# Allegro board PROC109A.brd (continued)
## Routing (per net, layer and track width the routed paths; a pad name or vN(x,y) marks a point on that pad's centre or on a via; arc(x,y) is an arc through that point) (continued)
GPIO1_0: length 86
  TOP w0.102: v2(80.41,-47.86) 80.48,-47.81 U18.J3
  L03_SIG1 w0.121: v2(80.41,-47.86) 79.64,-48.63 79.64,-51.8 79.91,-52.07 79.91,-53.92 79.35,-54.48 79.35,-55.89 79.7,-56.24 v1(80.65,-56.24)
  BOTTOM w0.135: v1(80.65,-56.24) 80.36,-56.54 74.4,-56.54 73.39,-57.55 66.59,-57.55 66.53,-57.5 66.44,-57.5 64.4,-55.46 62.77,-55.46 62.16,-54.85 57.62,-54.85 57.61,-54.84 53.45,-54.84 52.45,-53.85 49.73,-53.85 46.54,-50.65 46.54,-40.66 49.28,-37.92 49.76,-37.92 53.89,-33.79 53.89,-23.96 58.53,-19.32 J2.15
GPIO1_1: length 83
  TOP w0.102: v2(80.41,-47.29) 80.46,-47.31 U18.J4
  L03_SIG1 w0.121: v2(80.41,-47.29) 80.78,-47.66 80.78,-51.54 80.31,-52 80.31,-55.32 v1(79.89,-55.74)
  BOTTOM w0.135: v1(79.89,-55.74) 79.44,-55.74 79.18,-56 73.97,-56 73.01,-56.96 66.75,-56.96 64.72,-54.92 63,-54.92 62.38,-54.3 53.69,-54.3 52.56,-53.17 50.05,-53.17 47.67,-50.79 47.67,-43.77 48.67,-42.77 48.67,-41.5 53.02,-37.15 53.02,-36.36 57.08,-32.3 57.08,-23.87 61.07,-19.88 J2.17
GPIO1_2: length 77.3
  TOP w0.102: U18.G1 79.89,-49.11 79.71,-49.3 79.71,-49.62
  TOP w0.135: 79.71,-49.62 79.71,-50.14 78.56,-51.28 78.56,-54.41 v1(77.67,-55.3)
  BOTTOM w0.135: J2.19 63.61,-19.32 59.88,-23.05 59.88,-32.7 49.4,-43.18 49.4,-45.57 48.51,-46.46 48.51,-50.49 50.38,-52.36 70.6,-52.36 72.69,-54.46 73.77,-54.46 74.61,-55.3 v1(77.67,-55.3)
GPIO1_3: length 93.5
  TOP w0.102: U18.H1 80.39,-49.12 80.53,-49.26 80.53,-49.58
  TOP w0.135: v1(80.37,-58.12) 78.83,-56.58 78.83,-51.68 79.63,-50.88 80.19,-50.88 80.53,-50.53 80.53,-49.58
  BOTTOM w0.135: J2.4 42.04,-16.74 42.04,-19.84 48.06,-25.86 48.06,-29.2 47.17,-30.08 47.17,-34.13 45.86,-35.45 45.86,-38.85 43.84,-40.87 43.84,-50.43 43.84,-51.51 49.7,-57.37 49.7,-57.37 49.71,-57.37 49.72,-57.38 49.98,-57.38 49.99,-57.38 50.02,-57.38 58.65,-57.38 58.81,-57.22 63.87,-57.22 65.77,-59.11 65.82,-59.11 66.38,-59.67 66.38,-60 67.1,-60.73 75.8,-60.73 78.02,-58.51 79.52,-58.51 79.92,-58.12 v1(80.37,-58.12)
GPIO1_4: length 91
  TOP w0.102: U18.K2 81.39,-48.42 81.11,-48.7 81.11,-48.93 81.34,-49.15 81.34,-49.66
  TOP w0.135: v1(82.42,-56.63) 82.42,-55.45 81.34,-54.36 81.34,-49.66
  BOTTOM w0.135: J2.8 47.09,-16.77 47.09,-22.73 48.59,-24.24 48.59,-29.93 48.56,-29.97 48.56,-33.09 48.59,-33.13 48.59,-33.54 47.64,-34.5 47.64,-37.96 44.6,-41 44.6,-50.24 51.2,-56.84 53.32,-56.84 58.17,-56.84 58.34,-56.67 64.09,-56.67 65.99,-58.57 66.04,-58.57 66.92,-59.45 66.92,-59.78 67.32,-60.19 73.84,-60.19 76,-58.03 76.42,-58.03 76.95,-58.56 77.37,-58.56 78.57,-57.36 82.14,-57.36 82.42,-57.08 v1(82.42,-56.63)
GPIO1_5: length 85.8
  TOP w0.102: U18.F2 79.38,-48.33 79.38,-49.01 79.17,-49.22 79.17,-49.66
  TOP w0.135: 79.17,-49.66 79.17,-49.92 78.52,-50.57 78.44,-50.57 77.27,-51.74 77.01,-51.74 76.73,-52.02 76.73,-56.31 v1(77.39,-56.97)
  BOTTOM w0.135: J2.16 57.25,-16.77 57.25,-19.58 52.58,-24.26 52.58,-33.81 48.77,-37.62 48.77,-37.97 46.18,-40.56 46.18,-50.67 51.54,-56.03 52.52,-56.03 57.63,-56.03 58.55,-55.12 62.05,-55.12 62.66,-55.73 64.29,-55.73 66.32,-57.76 66.42,-57.76 66.47,-57.82 73.55,-57.82 74.4,-56.97 v1(77.39,-56.97)
GPIO1_6: length 56
  TOP w0.102: U18.H2 80.71,-48.63 80.71,-49.1 80.8,-49.19 80.8,-49.66
  TOP w0.135: J5.15 119.18,-64.06 101.02,-64.06 98.68,-61.72 86.49,-61.72 83.02,-58.25 81.75,-58.25 79.63,-56.14 79.63,-56.09 79.46,-55.92 79.46,-55.56 79.63,-55.39 79.63,-52.98 79.91,-52.71 79.91,-51.99 79.68,-51.77 79.68,-51.41 79.93,-51.16 80.53,-51.16 80.8,-50.89 80.8,-49.66
GPIO1_8: length 108
  TOP w0.102: U18.H5 80.35,-46.81 79.87,-47.29 v2(79.85,-47.29)
  L03_SIG1 w0.121: v1(130.73,-56.59) 130.4,-56.26 125.66,-56.26 125.12,-56.79 107.07,-56.79 106.51,-56.24 98.22,-56.24 97.06,-57.4 89.31,-57.4 89.15,-57.57 81.82,-57.57 81.18,-56.93 79.66,-56.93 78.61,-55.88 78.61,-51.77 78.77,-51.61 78.77,-48.38 v2(79.85,-47.29)
  BOTTOM w0.135: v1(130.73,-56.59) 131.19,-56.14 131.19,-41.99 131.65,-41.52 131.65,-37.12 131.65,-30.61 131.19,-30.14 131.19,-18.16 128.52,-15.49 J6.20
GPIO1_12: length 52.6
  TOP w0.102: 81.61,-49.53 81.61,-49.03 U18.K1
  TOP w0.135: 81.61,-49.53 81.61,-54.05 84.57,-57.01 84.57,-58.81 v1(86.54,-60.78)
  BOTTOM w0.135: J1.9 52.69,-62.99 66.09,-62.99 67.55,-61.53 76.31,-61.53 78.51,-59.33 85.08,-59.33 v1(86.54,-60.78)
GPIO1_18: length 50.1
  TOP w0.102: U18.K4 v2(81.39,-47.86)
  L03_SIG1 w0.121: v2(81.39,-47.86) 81.65,-48.12 81.65,-54.89 v1(83.39,-56.63)
  BOTTOM w0.135: U50.1 91.42,-56.1 90.95,-55.63 88.02,-55.63 87.36,-54.97 86.81,-54.97 85.15,-56.63 v1(83.39,-56.63) 81.23,-58.78 79.27,-58.78 ; 79.27,-58.78 78.3,-58.78 76.08,-60.99 67.1,-60.99 65.64,-62.45 59.77,-62.45 J1.15 ; 79.27,-58.78 79.27,-58.79
GPIO1_19: length 51.2
  TOP w0.102: 79.44,-49.61 79.44,-49.24 79.58,-49.1 79.58,-48.63 U18.G2
  TOP w0.135: v1(77.19,-58.13) 77.82,-57.49 77.82,-56.34 77.14,-55.65 77.14,-53.31 77.65,-52.81 77.65,-51.81 79.44,-50.03 79.44,-49.61
  L03_SIG1 w0.121: J5.9 112.91,-62.71 99.45,-62.71 97.22,-60.49 91.1,-60.49 89.46,-58.85 77.91,-58.85 v1(77.19,-58.13)
GPIO1_20: length 88
  TOP w0.102: U18.L5 81.44,-46.81 v2(81.39,-46.77)
  L03_SIG1 w0.121: v2(81.39,-46.77) 81.03,-47.14 81.03,-49.55 81.4,-49.92 81.4,-55.54 v1(81.41,-55.55)
  BOTTOM w0.135: v1(81.41,-55.55) 81.09,-55.23 79.39,-55.23 78.89,-55.73 73.83,-55.73 72.88,-56.69 66.86,-56.69 64.83,-54.65 63.11,-54.65 62.49,-54.03 53.81,-54.03 52.67,-52.9 50.16,-52.9 47.94,-50.68 47.94,-46.27 48.82,-45.39 48.82,-43.01 54.23,-37.6 54.23,-36.02 57.73,-32.51 57.73,-30 58.53,-29.2 58.53,-23.13 62.33,-19.33 62.33,-16.77 J2.20
GPIO1_21: length 53.3
  TOP w0.102: U18.J2 80.91,-48.33 80.91,-49.01 81.07,-49.17 81.07,-49.62
  TOP w0.135: 81.07,-49.62 81.07,-51.24 80.32,-51.99 80.32,-55.17 86.6,-61.45 98.79,-61.45 101.13,-63.79 116.39,-63.79 118.24,-61.95 118.24,-59.92 J5.14
GPIO1_22: length 48.6
  TOP w0.102: U18.M2 82.39,-49.25 82.63,-49.48
  TOP w0.135: 82.63,-49.48 82.63,-50.37 83.13,-50.87 83.13,-53.92 85.38,-56.17 85.38,-57.11 86.23,-57.96 96.92,-57.96 98.06,-56.83 102.96,-56.83 103.33,-56.46 105.33,-56.46 106.28,-57.41 120.76,-57.41 J5.16
GPIO1_26: length 59.8
  TOP w0.102: U18.F5 v2(79.39,-46.36)
  TOP w0.135: J5.18 122.62,-56.73 117.36,-56.73 116.99,-57.1 115.47,-57.1 115.1,-56.73 v1(106.4,-56.73)
  L03_SIG1 w0.121: v1(106.4,-56.73) 106.24,-56.57 98.37,-56.57 97.28,-57.66 89.42,-57.66 89.25,-57.82 81.62,-57.82 80.98,-57.18 79.51,-57.18 78.26,-55.93 78.26,-54.69 77.65,-54.08 77.65,-51.54 78.46,-50.72 78.46,-48.35 79.39,-47.42 v2(79.39,-46.36)
GPIO1_31: length 52.3
  TOP w0.102: U18.P1 83.39,-49.41 83.58,-49.59
  TOP w0.135: J5.20 124.6,-56.16 117.55,-56.16 116.99,-56.72 116.09,-56.72 116.05,-56.76 115.7,-56.76 115.66,-56.72 115.47,-56.72 114.92,-56.16 103.25,-56.16 102.85,-56.56 97.95,-56.56 96.81,-57.69 87.57,-57.69 86.7,-56.83 86.7,-54.92 83.96,-52.19 83.96,-50.56 83.58,-50.17 83.58,-49.59
GPIO1_32: length 96.2
  TOP w0.102: U18.P2 83.71,-48.63 83.71,-49.34 83.85,-49.48
  TOP w0.135: v1(129.59,-55.45) 129.14,-55.9 117.43,-55.9 116.88,-56.45 116.44,-56.45 116.31,-56.31 116.31,-55.96 116.24,-55.9 103.13,-55.9 102.74,-56.29 97.84,-56.29 96.7,-57.43 87.9,-57.43 87.73,-57.25 87.73,-55.28 85.09,-52.64 85.09,-51.31 83.85,-50.06 83.85,-49.48
  BOTTOM w0.135: J6.17 126.78,-20.24 128.68,-20.24 130.36,-21.93 130.36,-30.46 130.85,-30.94 130.85,-37.45 130.85,-41.19 130.38,-41.66 130.38,-50.75 129.13,-51.99 129.13,-54.99 v1(129.59,-55.45)
GPIO1_33: length 85.2
  TOP w0.102: v2(84.93,-47.33) 84.92,-47.31 U18.T4
  L03_SIG1 w0.121: v2(84.93,-47.33) 85.33,-46.93 88,-46.93 89.06,-47.99 101.45,-47.99 101.83,-48.36 102.74,-48.36 104.34,-49.96 106.55,-49.96 107.72,-51.13 110.69,-51.13 111.75,-52.19 115.67,-52.19 116.15,-51.71 117.34,-51.71 118.53,-52.9 124.47,-52.9 124.81,-52.56 v1(129.57,-52.56)
  BOTTOM w0.135: J6.19 130.63,-21.56 130.63,-30.35 131.12,-30.83 131.12,-37.34 131.12,-41.3 130.65,-41.77 130.65,-51.48 v1(129.57,-52.56)
GPIO1_35: length 88.4
  TOP w0.102: U18.M4 81.93,-47.31 v2(81.91,-47.29)
  L03_SIG1 w0.121: v2(81.91,-47.29) 81.91,-54.48 84.41,-56.97 85.19,-56.97 85.83,-56.34 89,-56.34 89.56,-56.89 96.68,-56.89 97.89,-55.68 112.92,-55.68 113.15,-55.45 v1(113.59,-55.45)
  BOTTOM w0.135: J6.4 105.51,-16.77 105.51,-20.52 105.23,-20.8 105.23,-21.49 105.68,-21.94 110.02,-21.94 110.26,-22.17 110.26,-24.34 111.46,-25.54 111.46,-32.12 111.48,-32.15 111.48,-34.34 113.99,-36.85 113.99,-36.85 114,-36.87 114,-36.88 114.01,-36.89 114.01,-50.81 114,-50.82 114,-50.84 113.99,-50.85 113.99,-50.86 113.59,-51.26 v1(113.59,-55.45)
GPIO1_36: length 37.5
  TOP w0.102: v2(83.94,-47.86) 83.98,-47.81 U18.T3
  L03_SIG1 w0.102: v2(83.94,-47.86) 83.94,-48.22 85.37,-49.66
  L03_SIG1 w0.121: v1(116.18,-52.93) 115.95,-52.7 110.84,-52.7 109.99,-51.85 98.79,-51.85 97.46,-50.52 86.23,-50.52 85.37,-49.66
  BOTTOM w0.135: v1(116.18,-52.93) 116.51,-52.6 116.51,-52.1 116.74,-51.87 U52.3
GPIO1_36/PERIF_OUT_EN: length 59.3
  TOP w0.135: J6.8 113.08,-16.7 113.08,-18.54 114.33,-19.79 115.57,-19.79 116.15,-20.37 116.71,-20.37 116.76,-20.32 119.94,-20.32 123.11,-23.5 123.11,-27.58 120.02,-30.68 120.02,-32.56 120.56,-33.11 120.93,-33.11 122.76,-34.94 124.08,-34.94 125.67,-36.52 125.67,-36.88 124.81,-37.74 124.81,-38.15 125.07,-38.41 125.07,-40.41 124.54,-40.94 124.54,-45.11 123.88,-45.77 123.88,-48.79 122.9,-49.77 121.27,-49.77 119.09,-51.96 116.75,-51.96 116.36,-51.56 116.36,-50.46 v1(116.92,-49.89) 116.92,-49.88
  BOTTOM w0.135: U52.5 118.09,-50.55 117.94,-50.39 117.33,-50.39 117.2,-50.26 117.2,-50.11 116.97,-49.89 116.97,-49.89 v1(116.92,-49.89)
GPIO1_40: length 117.7
  TOP w0.102: U18.E4 78.36,-46.78 v2(78.36,-46.77)
  L03_SIG1 w0.121: v1(54.61,-39.24) 54.61,-40.23 56.07,-41.69 63.64,-41.69 66.22,-44.27 66.22,-45.15 69.52,-48.46 71.7,-48.46 73.47,-50.23 74.3,-50.23 77.76,-46.77 v2(78.36,-46.77)
  BOTTOM w0.135: J6.16 119.24,-12.71 86.4,-12.71 84.42,-14.68 84.42,-15.52 82.82,-17.12 66.44,-17.12 62.84,-20.73 62.84,-26.45 60.49,-28.8 60.49,-33.36 v1(54.61,-39.24)
GPIO1_41: length 124.3
  TOP w0.102: U18.D2 78.11,-48.6 78.11,-49.33 77.78,-49.66
  TOP w0.135: 77.78,-49.66 77.23,-50.21 77.22,-50.21 76.78,-50.65 76.48,-50.65 75.37,-51.75 75.37,-59.02 75.68,-59.32 78.01,-59.32 78.52,-58.82 82.83,-58.82 86.3,-62.3 98.5,-62.3 100.8,-64.6 100.82,-64.6 101.02,-64.8 120.17,-64.8 120.28,-64.91 127.44,-64.91 128.15,-64.2 129.33,-64.2 129.44,-64.31 129.55,-64.31 129.83,-64.59 v1(130.28,-64.59)
  BOTTOM w0.135: v1(130.28,-64.59) 130.28,-55.91 130.92,-55.27 130.92,-41.88 131.39,-41.41 131.39,-37.23 131.39,-30.72 130.9,-30.24 130.9,-19.08 128.58,-16.76 125.84,-16.76 J6.18
GPIO1_61: length 2.6
  TOP w0.135: TP34.1 158.72,-51.4 U22.7
GPIO1_77: length 98.5
  TOP w0.102: U18.B17 77.11,-41.09 76.48,-41.09 76.33,-40.94 76.05,-40.94
  TOP w0.135: v1(68.35,-38.58) 68.38,-38.55 70.33,-38.55 71.98,-40.21 72.8,-40.21 73.53,-40.94 76.05,-40.94
  BOTTOM w0.135: J6.13 118.21,-16.76 118.21,-14.83 116.35,-12.98 86.51,-12.98 84.69,-14.79 84.69,-15.63 82.93,-17.39 82.71,-17.39 66.55,-17.39 63.11,-20.84 63.11,-24.2 68.16,-29.25 71.41,-29.25 72.14,-29.97 72.14,-31.5 69.62,-34.02 69.62,-34.52 68.35,-35.79 v1(68.35,-38.58)
GPIO1_78: length 107.7
  TOP w0.102: U18.C16 77.89,-41.74 v2(77.86,-41.77)
  TOP w0.135: J6.15 120.78,-16.79 120.78,-14.53 119.39,-13.14 85.34,-13.14 81.81,-16.66 76.91,-16.66 75.11,-14.86 69.62,-14.86 67.61,-16.87 67.61,-29.62 66.66,-30.57 63.33,-30.57 62.51,-31.39 62.51,-36.34 61.89,-36.95 v1(61.89,-38.56)
  L03_SIG1 w0.121: v2(77.86,-41.77) 77.6,-42.03 77.15,-42.03 76.35,-42.82 71.15,-42.82 69.75,-44.22 67.94,-44.22 67.44,-43.71 67.44,-41.87 66.52,-40.94 64.75,-40.94 62.37,-38.56 v1(61.89,-38.56)
GPIO_OSPI0_RESET_N: length 36
  TOP w0.102: U18.M20 82.69,-39.02 82.69,-38.42 83.06,-38.04 83.06,-37.97
  TOP w0.135: 83.06,-37.97 83.06,-31.9 85.29,-29.67 85.29,-23.3 83.53,-21.54 v1(83.08,-21.54)
  BOTTOM w0.135: 75.2,-21.06 75.2,-21.45 75.74,-21.99 U31.1 ; 75.2,-21.06 75.75,-21.06 75.9,-20.92 75.9,-18.85 76.25,-18.49 83.16,-18.49 83.79,-19.13 83.79,-20.83 v1(83.08,-21.54) ; 75.2,-21.06 R181.1
GPIO_RGMII1_PHY_RSTN: length 100.7
  TOP w0.102: U18.Y19 86.67,-40.09 87.16,-40.09 87.74,-39.52 87.74,-39.49
  TOP w0.135: v1(95.6,-36.08) 95.15,-36.08 95.13,-36.09 94.08,-36.09 93.15,-37.02 90.21,-37.02 87.74,-39.49
  L03_SIG1 w0.121: v1(113.45,-33.31) 110.73,-36.03 102.2,-36.03 101.85,-35.69 99.19,-35.69 98.8,-36.08 v1(95.6,-36.08)
  BOTTOM w0.135: U43.1 142.44,-56.37 142.58,-56.22 142.58,-55.81 ; v1(113.45,-33.31) 113.45,-34.45 115.39,-36.4 115.39,-53.98 117.87,-56.45 118.26,-56.86 118.26,-62.66 120.62,-65.02 126.19,-65.02 126.88,-65.72 126.89,-65.72 126.9,-65.73 126.91,-65.73 126.93,-65.74 128.83,-65.74 128.84,-65.73 128.85,-65.73 128.87,-65.72 129,-65.58 129.23,-65.63 129.25,-65.63 129.49,-65.63 132.72,-65.63 132.74,-65.63 132.75,-65.62 133.44,-64.94 133.45,-64.92 133.45,-64.9 133.45,-55.68 135.48,-53.65 136.86,-53.65 136.88,-53.64 136.98,-53.65 137.62,-53.65 138.66,-54.69 140.79,-54.69 141.92,-55.81 142.58,-55.81 ; 142.58,-55.81 R275.1
GPIO_RGMII2_PHY_RSTN: length 63
  TOP w0.102: U18.Y15 87.56,-41.82 87.62,-41.88 87.74,-41.88
  TOP w0.135: 87.74,-41.88 94.47,-41.88 97.52,-38.83 101.88,-38.83 102.49,-38.23 104.85,-38.23 106.79,-36.29 108.46,-36.29 108.68,-36.07 121.69,-36.07 122.76,-37.13 123.7,-37.13 v1(124.16,-37.59)
  L03_SIG1 w0.121: v1(140.97,-35.56) 140.66,-35.87 139.35,-35.87 138.87,-35.39 138.19,-35.39 137.92,-35.66 125.15,-35.66 124.47,-36.34 124.47,-37.28 v1(124.16,-37.59)
  BOTTOM w0.135: 142.03,-36.76 R236.1 ; 142.03,-36.76 141.73,-37.06 141.17,-37.06 140.92,-36.81 U34.1 ; 142.03,-36.76 141.29,-36.02 141.29,-35.88 v1(140.97,-35.56)
LED1: length 45.5
  TOP w0.135: LD15.1 v1(176.75,-64.55)
  L03_SIG1 w0.121: v1(159.44,-34.67) 158.37,-35.74 158.37,-51.39 159.73,-52.75 159.73,-54.15 165.12,-59.54 166.42,-59.54 167.67,-60.78 167.67,-61.54 171.7,-65.58 175.72,-65.58 v1(176.75,-64.55)
  BOTTOM w0.135: v1(159.44,-34.67) U35.3
LED2: length 42.2
  TOP w0.135: LD14.1 v1(175.23,-64.55)
  L03_SIG1 w0.121: v1(159.44,-35.94) 158.62,-36.75 158.62,-51.28 160.02,-52.68 160.02,-54.08 165.23,-59.28 167.21,-59.28 170.33,-62.41 170.33,-63.65 171.96,-65.28 174.5,-65.28 v1(175.23,-64.55)
  BOTTOM w0.135: U35.4 v1(159.44,-35.94)
LED3: length 38.9
  TOP w0.135: LD13.1 v1(173.73,-64.55)
  L03_SIG1 w0.121: v1(173.73,-64.55) 173.26,-65.02 172.08,-65.02 170.81,-63.75 170.81,-62.48 167.36,-59.03 165.33,-59.03 160.32,-54.02 160.32,-49.89 158.88,-48.44 158.88,-37.77 v1(159.44,-37.21)
  BOTTOM w0.135: U35.5 v1(159.44,-37.21)
LED4: length 35.1
  TOP w0.135: LD12.1 v1(172.23,-64.55)
  L03_SIG1 w0.121: v1(159.44,-38.48) 159.16,-38.76 159.16,-47.85 160.59,-49.28 160.59,-53.92 165.43,-58.77 167.48,-58.77 172.23,-63.52 v1(172.23,-64.55)
  BOTTOM w0.135: U35.6 v1(159.44,-38.48)
LED_DRV_A0: length 2.6
  BOTTOM w0.135: U35.9 151.03,-41.02 150.93,-41.12 R245.2
LED_DRV_A1: length 2.6
  BOTTOM w0.135: R241.2 150.77,-39.6 150.93,-39.75 U35.10
LED_DRV_A2: length 2.9
  BOTTOM w0.135: U35.7 159.44,-39.75 159.66,-39.97 R243.2
LMK_1G: length 1.9
  TOP w0.135: U6.2 R32.1
LMK_CLK_IN: length 2.6
  TOP w0.135: U6.1 117.21,-25.19 116.93,-24.91 R26.2
LMK_CLK_IN_R: length 1.6
  TOP w0.135: R26.1 114.61,-24.32 U3.3
MAIN_UART0_RXD: length 63.3
  TOP w0.102: 76.05,-44.74 76.16,-44.74 76.23,-44.67 76.25,-44.67 76.61,-44.31 U18.B10
  TOP w0.135: 76.05,-44.74 73.38,-44.74 73.21,-44.91 71.83,-44.91 71.62,-44.7 69.75,-44.7 68.66,-45.8 67.26,-45.8 65.58,-44.11 63.53,-44.11 62.65,-44.99 v1(62.65,-45.63)
  L03_SIG1 w0.127: v1(62.65,-45.63) 63.22,-46.19 63.22,-53.55 60.6,-56.16 40.89,-56.16 34.39,-62.66 32.51,-62.66 32.05,-62.2 v1(32.05,-61.59)
  BOTTOM w0.135: U45.6 32.98,-61.2 32.59,-61.59 v1(32.05,-61.59)
MAIN_UART0_TXD: length 61.5
  TOP w0.102: 76.05,-44.47 76.16,-44.47 76.32,-44.31 76.32,-44.25 76.46,-44.11 77.1,-44.11 U18.B11
  TOP w0.135: 76.05,-44.47 73.26,-44.47 73.14,-44.6 71.9,-44.6 71.73,-44.43 69.62,-44.43 69.16,-44.88 66.8,-44.88 65.56,-43.64 63.45,-43.64 62.2,-44.88 62.2,-46.22 v1(62.57,-46.58)
  L03_SIG1 w0.121: v1(33.15,-61.65) 34.06,-60.73 35,-60.73 40.97,-54.76 60.55,-54.76
  L03_SIG1 w0.127: 60.55,-54.76 61.87,-53.44 61.87,-47.27 v1(62.57,-46.58)
  BOTTOM w0.135: v1(33.15,-61.65) 33.15,-62.12 R592.1 33.9,-61.97 33.9,-61.5 34.28,-61.11 U45.4
MAIN_UART1_CTS#: length 72.1
  TOP w0.102: v2(77.86,-43.36) 77.89,-43.39 U18.C11
  TOP w0.135: U12.11 98.65,-33.65 98.02,-34.29 98.02,-36.8 97.43,-37.39 93.96,-37.39 93.55,-37.8 v1(92.33,-37.8)
  L03_SIG1 w0.102: 77.06,-43.94 77.28,-43.94 v2(77.86,-43.36)
  L03_SIG1 w0.127: v1(68.1,-45.34) 68.61,-45.86 75.15,-45.86 77.06,-43.94
  BOTTOM w0.135: v1(92.33,-37.8) 92.33,-38.24 92.58,-38.5 92.58,-40.36 94.03,-41.81 94.03,-50.38 90.42,-53.99 88.67,-53.99 88.03,-53.35 86.07,-53.35 85.58,-53.84 75.02,-53.84 72.33,-51.15 68.82,-51.15 68.32,-50.65 68.32,-49.87 67.78,-49.32 67.78,-45.66 v1(68.1,-45.34)
MAIN_UART1_RTS#: length 107.9
  TOP w0.114: U18.A11 76.44,-43.81 76.32,-43.94
  TOP w0.135: v1(97.46,-64.02) 96.41,-64.02 95.76,-63.38 85.86,-63.38 82.38,-59.9 78.96,-59.9 78.12,-60.74 67.21,-60.74 66.57,-60.09 66.57,-56.47 66.78,-56.26 66.78,-52.68 66,-51.9 66,-51.21 65.46,-50.67 65,-50.67 63.22,-48.89 63.22,-47.98 61.94,-46.7 61.94,-44.77 63.34,-43.37 65.85,-43.37 67.09,-44.61 69.03,-44.61 69.48,-44.16 71.9,-44.16 72.07,-44.33 73.02,-44.33 73.15,-44.2 76.06,-44.2 76.32,-43.94 ; v1(108.9,-32.99) 108.89,-33.01 U12.5
  BOTTOM w0.135: v1(97.46,-64.02) 98.1,-64.02 98.68,-63.44 98.68,-58.11 97.97,-57.41 97.97,-51.11 97.76,-50.9 97.76,-40.31 105.08,-32.99 v1(108.9,-32.99)
MAIN_UART1_RXD: length 105
  TOP w0.102: 76.05,-43.44 76.46,-43.04 77.11,-43.04 U18.B12
  TOP w0.135: v1(102.95,-31.67) 102.91,-31.71 U12.8 ; 76.05,-43.44 75.83,-43.66 74.04,-43.66 73.39,-43.01 71.59,-43.01 71.04,-43.56 69.32,-43.56 69.09,-43.79 68.81,-44.07 67.65,-44.07 66.4,-42.83 62.99,-42.83 61.4,-44.42 61.4,-47.16 61.99,-47.75 61.99,-48.91 66.24,-53.16 66.24,-55.98 66.03,-56.19 66.03,-60.37 66.94,-61.27 78.35,-61.27 79.19,-60.44 82.16,-60.44 85.85,-64.13 v1(95.38,-64.13)
  BOTTOM w0.135: v1(102.95,-31.67) 102.63,-31.98 102.63,-32.41 98.35,-36.7 98.35,-37.71 96.68,-39.38 96.68,-51.34 96.89,-51.55 96.89,-58.88 97.02,-59 97.02,-62.02 95.38,-63.66 v1(95.38,-64.13)
MAIN_UART1_TXD: length 108.5
  TOP w0.102: U18.A12 76.6,-43.61 76.27,-43.61 76.05,-43.82
  TOP w0.135: 76.05,-43.82 75.95,-43.93 73.04,-43.93 72.91,-44.06 72.23,-44.06 72.06,-43.89 69.37,-43.89 68.92,-44.34 67.3,-44.34 66.06,-43.1 63.1,-43.1 61.67,-44.53 61.67,-46.93 62.26,-47.53 62.26,-48.8 66.51,-53.05 66.51,-56.14 66.3,-56.36 66.3,-60.25 67.05,-61.01 78.24,-61.01 79.07,-60.17 82.27,-60.17 85.81,-63.7 95.71,-63.7 96.46,-64.45 98.67,-64.45 v1(99.11,-64.01) ; v1(108.9,-34.95) 108.84,-34.95 108.83,-34.95 U12.2
  BOTTOM w0.135: v1(99.11,-64.01) 99.11,-58.17 98.24,-57.29 98.24,-50.99 98.03,-50.79 98.03,-40.68 103.76,-34.95 v1(108.9,-34.95)
MAIN_UART2_RXD: length 132.8
  L03_SIG1 w0.121: J1.5 48.77,-64.16 65.15,-64.16 66.22,-65.23 68.83,-65.23 68.84,-65.23 68.85,-65.23 68.86,-65.22 68.87,-65.21 73.68,-60.41 85.92,-60.41 86.11,-60.61 86.11,-60.96 86.36,-61.21 87.81,-61.21 92.65,-66.05 127.96,-66.05 v1(129.29,-64.72)
  BOTTOM w0.135: v1(129.29,-64.72) 129.29,-64.27 129.29,-64.26 129.29,-55.78 128.83,-55.32 128.83,-51.92 130.11,-50.64 130.11,-41.47 130.58,-41 130.58,-37.56 130.58,-31.05 129.69,-30.17 126.43,-30.17 125.95,-29.68 125.95,-28.39 125.66,-28.11 U32.16
MAIN_UART2_TXD: length 105.3
  TOP w0.102: 84.48,-37.97 84.48,-38.18 84.19,-38.47 84.19,-39.02 U18.R20
  TOP w0.135: 84.48,-37.97 84.48,-37.67 85.05,-37.1 85.05,-35.45 88.52,-31.98 v1(88.52,-30.81) 88.52,-29.83 R56.1
  L03_SIG1 w0.121: v1(38.3,-27.81) 43.15,-27.81 43.38,-28.04 55.28,-28.04 55.8,-28.57 64.72,-28.57 68.95,-24.33 72.21,-24.33 72.85,-24.98 82.39,-24.98 84.1,-26.69 84.1,-27.63 85.74,-29.27 87.95,-29.27 88.52,-29.84 v1(88.52,-30.81)
  BOTTOM w0.135: v1(38.3,-27.81) 38.86,-28.37 38.86,-32.58 40.49,-34.21 40.88,-34.21 41.43,-34.77 41.43,-49.56 47.09,-55.22 47.09,-59.94 J1.7
MAIN_UART4_RXD: length 22.4
  TOP w0.102: U18.L1 81.89,-49.66
  TOP w0.135: 81.89,-49.66 81.89,-53.45 84.84,-56.39 84.84,-57.33 88.56,-61.05 92.77,-61.05 92.87,-60.95 v1(93.32,-60.95)
  BOTTOM w0.135: v1(93.32,-60.95) 93.23,-61.04 92.84,-61.04 92.62,-60.82 U50.9 U50.4
MAIN_UART4_RXD/GPIO1_69: length 18.7
  TOP w0.135: v1(93.96,-60.01) 93.94,-60 93.94,-59.92 94.26,-60.24 94.63,-60.6 98.32,-60.6 101.24,-63.53 107.01,-63.53 J5.5
  BOTTOM w0.135: U50.7 93.84,-60.04 93.87,-60.01 v1(93.96,-60.01)
MAIN_UART4_TXD: length 48.5
  TOP w0.102: U18.E2 79.17,-48.59 79.17,-48.93 78.9,-49.21 78.9,-49.66
  TOP w0.135: 78.9,-49.66 78.9,-49.8 78.4,-50.3 78.33,-50.3 77.16,-51.47 76.91,-51.47 76.47,-51.91 76.47,-58.1 77.04,-58.67 77.86,-58.67 v1(78.45,-58.08)
  L03_SIG1 w0.127: J5.7 110.62,-59.97 97.38,-59.97 96.95,-59.54 94.81,-59.54 94.66,-59.68 94.28,-59.68 94.06,-59.46 90.43,-59.46 89.56,-58.59 89.52,-58.59 78.96,-58.59 v1(78.45,-58.08)
MCAN0_H: length 9.4
  BOTTOM w0.104: U44.7 164.52,-57.97 164.71,-58.15 164.71,-58.85 R278.1 164.35,-59.75 164.45,-59.85 164.57,-59.85 164.67,-59.96 164.67,-60.52 165.61,-61.46 165.61,-62.84 165.4,-63.04 164.16,-63.04 163.3,-63.9 J11.1
MCAN0_L: length 9.3
  BOTTOM w0.104: J11.3 167.19,-63.04 166.09,-63.04 165.89,-62.84 165.89,-61.34 164.95,-60.4 164.95,-59.96 165.05,-59.85 165.17,-59.85 165.27,-59.75 R277.2 164.98,-58.92 164.98,-58.15 165.17,-57.97 U44.6
MCAN0_RX: length 9.7
  BOTTOM w0.135: R263.2 160.87,-51.12 161.34,-50.65 165.94,-50.65 166.6,-51.31 166.6,-53.01 165.82,-53.79 U44.4
MCAN0_RX_MUX: length 114.9
  TOP w0.102: U18.A14 76.4,-42.32 76.3,-42.21 76.07,-42.21 76.05,-42.19
  TOP w0.135: 76.05,-42.19 71.22,-42.19 70.79,-42.63 68.56,-42.63 68.28,-42.34 v1(68.25,-42.34) ; U22.6 v1(156.37,-51.9)
  L03_SIG1 w0.121: v1(92.46,-52.68) 92.88,-52.26 97.72,-52.26 99.82,-54.35 105.63,-54.35 105.85,-54.13 113.63,-54.13 113.63,-54.13 115.36,-54.13 116.6,-55.37 124.74,-55.37 125.61,-54.51 131.59,-54.51 132.64,-55.55 138.68,-55.55 139.39,-56.25 149.82,-56.25 153.26,-52.81 155.47,-52.81 v1(156.37,-51.9)
  BOTTOM w0.135: v1(68.25,-42.34) 67.42,-43.17 67.42,-50.41 68.43,-51.42 72.09,-51.42 74.78,-54.11 85.69,-54.11 86.18,-53.62 87.91,-53.62 88.56,-54.26 90.88,-54.26 v1(92.46,-52.68)
MCAN0_RX_SYNC3_OUT: length 3.7
  TOP w0.135: v1(159.89,-51.89) 159.89,-51.89 R131.1 159.64,-50.9 U22.8
  BOTTOM w0.135: v1(159.89,-51.89) 159.89,-51.16 R131.1
MCAN0_STB: length 104.3
  TOP w0.102: v2(78.44,-47.86) 78.48,-47.81 U18.E3
  L03_SIG1 w0.121: v1(158.17,-61.54) 157.08,-62.63 142.37,-62.63 140.16,-60.42 140.16,-59.06 138.17,-57.08 106.65,-57.08 106.58,-57.15 106.23,-57.15 105.94,-56.86 98.51,-56.86 97.46,-57.91 89.53,-57.91 89.36,-58.08 81.5,-58.08 80.86,-57.44 79.21,-57.44 76.69,-54.92 76.69,-52.01 78.03,-50.67 78.03,-48.27 v2(78.44,-47.86)
  BOTTOM w0.135: v1(158.17,-61.54) 160.88,-61.54 162.11,-60.32 R276.2 163.77,-58.12 163.87,-58.01 U44.8
MCAN0_T: length 6.1
  L03_SIG1 w0.121: v1(163.37,-60.17) v1(166.25,-60.17)
  BOTTOM w0.135: R278.2 v1(163.37,-60.17) ; R277.1 v1(166.25,-60.17) 166.51,-60.43 167.1,-60.43 C267.1
MCAN0_TX: length 3.7
  BOTTOM w0.135: U44.1 163.87,-53.86 163.52,-53.52 R259.2
MCAN0_TX_EQEP2_I: length 150.5
  TOP w0.102: 76.05,-42.82 U18.B13
  TOP w0.135: 76.05,-42.82 76.01,-42.82 75.95,-42.75 75.94,-42.75 75.93,-42.74 71.46,-42.74 70.93,-43.27 69.19,-43.27 68.66,-43.8 67.76,-43.8 66.51,-42.56 62.88,-42.56 61.13,-44.31 61.13,-47.27 61.72,-47.86 61.72,-49.02 65.13,-52.42 65.13,-55.55 65.76,-56.18 65.76,-60.48 66.98,-61.7 69.22,-61.7 v1(69.67,-62.15) ; U22.4 154.88,-51.4 156.08,-52.6 v1(158.55,-52.6)
  L03_SIG1 w0.121: v1(69.67,-62.15) 72.18,-59.64 87.33,-59.64 92.97,-65.28 118.66,-65.28 120.67,-63.27 137.93,-63.27 137.98,-63.32 138.05,-63.32 138.11,-63.37 138.2,-63.37 139.25,-64.42 145.08,-64.42 146.3,-63.2 157.28,-63.2 158.88,-61.59 158.88,-52.93 v1(158.55,-52.6)
MCAN0_TX_SYNC2_OUT: length 13.4
  TOP w0.135: U22.2 151.6,-50.4 v1(151.31,-50.7) 150.96,-51.04 R140.1
  BOTTOM w0.135: v1(151.31,-50.7) 151.62,-50.38 155.66,-50.38 158.8,-53.52 R259.1
MCAN/EQEP_SEL/PERIF_OUT_EN: length 65.4
  TOP w0.102: U18.F4 79.39,-47.28 78.92,-46.81 v2(78.92,-46.77)
  L03_SIG1 w0.121: v1(121.06,-53.97) 120.62,-53.97 120.44,-53.8 116.08,-53.8 115.5,-53.21 99.42,-53.21 97.54,-51.33 92.58,-51.33 92.02,-51.89 v1(90.7,-51.89) ; v1(73.69,-49.76) 74.42,-49.76 77.67,-46.51 78.1,-46.51 78.2,-46.41 78.56,-46.41 v2(78.92,-46.77)
  BOTTOM w0.135: U52.4 117.92,-51.5 118.31,-51.5 118.47,-51.66 118.47,-52.36 118.78,-52.67 U52.12 120.13,-52.67 120.4,-52.93 120.4,-53.31 v1(121.06,-53.97) ; v1(73.69,-49.76) 73.69,-51.36 75.9,-53.57 85.47,-53.57 85.96,-53.08 88.14,-53.08 88.78,-53.72 89.99,-53.72 90.7,-53.01 v1(90.7,-51.89)
MCU_PORZ: length 69.6
  TOP w0.102: U18.C20 77.89,-39.21 78.17,-38.93 78.17,-38.7 77.45,-37.97 77.42,-37.97
  TOP w0.135: v1(34.87,-18.06) 34.56,-18.38 33.11,-18.38 32.46,-19.02 TP1.1 31.72,-17.55 31.56,-17.39 U1.4 ; 77.42,-37.97 76.28,-36.83 76.28,-36.3 75.41,-35.43 75.11,-35.43 74.44,-34.76 74.44,-32.82 v1(74.12,-32.5)
  L03_SIG1 w0.121: v1(74.12,-32.5) 74.12,-31.24 72.52,-29.64 56.47,-29.64 55.15,-28.32 43.18,-28.32 42.95,-28.09 39.65,-28.09 39.32,-28.42 38.23,-28.42 37.59,-27.79 35.76,-27.79 35.18,-28.37 34.21,-28.37 33.08,-27.24 33.08,-23.84 35.26,-21.67 35.26,-18.44 v1(34.87,-18.06)
MCU_RESETSTATZ: length 91.9
  TOP w0.102: 76.05,-46.83 76.27,-46.61 76.6,-46.61 U18.A6
  TOP w0.135: 76.05,-46.83 75.31,-47.57 75.31,-47.58 74.27,-48.61 TP31.1 74.24,-49.28 R126.2 72.71,-49.8 73.1,-50.19 73.1,-53.06 71.86,-54.31 71.86,-55.2 v1(72.31,-55.65)
  L03_SIG1 w0.121: v1(76.56,-19.3) 75.47,-18.21 65.24,-18.21 63.87,-19.58 v1(62.74,-19.58)
  BOTTOM w0.135: v1(62.74,-19.58) 59.61,-22.71 59.61,-31.09 54.5,-36.21 54.5,-37.71 49.12,-43.08 49.12,-45.47 48.21,-46.38 48.21,-50.57 50.27,-52.63 52.79,-52.63 53.92,-53.77 62.6,-53.77 63.22,-54.38 64.94,-54.38 66.21,-55.65 v1(72.31,-55.65) ; R180.1 v1(76.56,-19.3)
MCU_RESETZ: length 30.1
  TOP w0.102: 76.05,-47.21 76.45,-46.81 U18.A5
  TOP w0.135: 76.05,-47.21 75.58,-47.69 75.58,-47.97 v1(74.78,-48.77) ; U13.7 59.26,-34.24 60.12,-35.1 TP19.1 61.44,-35.15 61.44,-40.54 v1(61.93,-41.02)
  L03_SIG1 w0.121: v1(61.93,-41.02) 63.42,-41.02 66.47,-44.07 66.47,-45.04 69.63,-48.2 72.25,-48.2 72.57,-48.52 74.53,-48.52 v1(74.78,-48.77)
MCU_SAFTY_ERRZ: length 5.6
  TOP w0.102: 76.6,-39.59 77.11,-39.59 U18.B20
  TOP w0.135: TP22.1 74.62,-37.72 76.5,-39.59 76.6,-39.59
MCU_UART0_CTS#: length 68.8
  TOP w0.102: v2(77.86,-47.86) 77.85,-47.85 77.86,-47.85 U18.D4
  TOP w0.135: U8.11 v1(103.1,-26.8)
  L03_SIG1 w0.121: v1(97.45,-59.35) 96.93,-58.83 90.17,-58.83 89.67,-58.33 89.63,-58.33 81.37,-58.33 80.72,-57.69 79.08,-57.69 76.44,-55.05 76.44,-51.78 77.6,-50.62 77.6,-48.12 v2(77.86,-47.86)
  BOTTOM w0.135: v1(97.45,-59.35) 97.45,-59 97.16,-58.72 97.16,-51.44 96.95,-51.23 96.95,-39.49 98.62,-37.83 98.62,-36.81 103.85,-31.57 103.85,-29.17 104.08,-28.94 104.08,-27.78 v1(103.1,-26.8)
MCU_UART0_RTS#: length 81.2
  TOP w0.102: 77.89,-49.16 77.89,-49.16 U18.C2
  TOP w0.114: 77.52,-49.53 77.89,-49.16
  TOP w0.135: 77.52,-49.53 77.52,-49.54 77.12,-49.94 77.11,-49.94 76.67,-50.38 76.36,-50.38 75.1,-51.64 75.1,-59.13 75.57,-59.59 78.12,-59.59 78.63,-59.09 82.71,-59.09 86.19,-62.57 97.75,-62.57 v1(98.12,-62.94) ; U8.5 108.89,-26.15 v1(108.9,-26.14)
  BOTTOM w0.135: v1(98.12,-62.94) 98.12,-62.49 98.27,-62.34 98.27,-59.03 97.7,-58.46 97.7,-51.22 97.49,-51.01 97.49,-40 107.85,-29.64 108.46,-29.64 109.4,-28.7 109.4,-26.64 v1(108.9,-26.14)
MCU_UART0_RXD: length 90.2
  TOP w0.102: v2(78.44,-45.86) 78.39,-45.9 U18.D6
  TOP w0.135: v1(99.36,-31.7) 99.36,-25.88 100.4,-24.85 U8.8
  L03_SIG1 w0.121: v1(66.73,-42.11) 66.73,-44.94 69.73,-47.95 72.46,-47.95 72.77,-48.26 75.26,-48.26 77.29,-46.23 78.07,-46.23 v2(78.44,-45.86)
  BOTTOM w0.135: v1(99.36,-31.7) 99.36,-32.33 97.27,-34.43 95.97,-34.43 92.85,-37.55 92.85,-40.25 94.54,-41.94 94.54,-52.27 92.01,-54.8 88.33,-54.8 87.69,-54.16 86.41,-54.16 85.92,-54.65 74.37,-54.65 71.68,-51.95 68.11,-51.95 66.88,-50.73 66.88,-42.27 v1(66.73,-42.11)
MCU_UART0_TXD: length 78.3
  TOP w0.102: U18.B2 77.69,-48.61 77.69,-49.01 76.99,-49.71 76.96,-49.71
  TOP w0.135: v1(108.9,-28.09) 108.84,-28.09 108.83,-28.1 U8.2 ; v1(96.82,-63.04) 96.38,-63.04 96.17,-62.84 86.08,-62.84 82.6,-59.36 78.74,-59.36 78.24,-59.86 75.46,-59.86 74.83,-59.24 74.83,-51.53 76.25,-50.11 76.56,-50.11 76.96,-49.71
  BOTTOM w0.135: v1(108.9,-28.09) 97.22,-39.77 97.22,-51.12 97.43,-51.33 97.43,-58.57 97.95,-59.09 97.95,-61.92 v1(96.82,-63.04)
OBSCLK0: length 108.2
  L03_SIG1 w0.121: v1(65.25,-20.22) 68.66,-20.22 69.36,-20.93 70.71,-20.93 71.12,-20.52 78.57,-20.52 78.93,-20.16 81.85,-20.16 82.52,-20.82 87.29,-20.82 89.51,-23.03 89.51,-23.04 89.54,-23.07 89.74,-23.27 93.67,-23.27 94.23,-23.83 95.12,-23.83 95.68,-23.27 99.6,-23.27 99.6,-23.27 101.26,-23.27 101.46,-23.47 102.23,-23.47 102.44,-23.27 107.75,-23.27 110.42,-20.6 114.67,-20.6 114.81,-20.74 115.16,-20.74 115.41,-20.5 120.25,-20.5 120.35,-20.59 120.7,-20.59 120.79,-20.5 132.89,-20.5 v1(135.53,-17.86)
  BOTTOM w0.135: R240.2 71.04,-39.45 70.33,-38.74 70.33,-36.98 70.46,-36.85 70.46,-34.31 73.18,-31.6 73.18,-29.87 71.04,-27.74 67.82,-27.74 63.92,-23.84 63.92,-21.17 64.87,-20.22 v1(65.25,-20.22) ; v1(135.53,-17.86) 137.77,-17.86 138.79,-18.88 R185.1
OSC0: length 8.6
  BOTTOM w0.135: Y1.3 11.5,-36.66 12.47,-35.69 14.55,-35.69 15.09,-36.23 C131.2 15.53,-36.25 15.78,-35.99 U37.88
OSC0_XO: length 6.7
  TOP w0.102: U18.C21 77.05,-37.97 76.73,-37.97
  TOP w0.135: 76.73,-37.97 74.8,-36.04 74.47,-36.04 73.72,-35.29 R78.2
OSC1: length 6.5
  BOTTOM w0.135: U37.89 15.71,-35.59 15.53,-35.41 C120.2 13.92,-35.41 Y1.1
OSC_STB#: length 2.1
  TOP w0.135: U3.1 112.21,-26.48 111.98,-26.71 R49.2
OSPI0_CLK: length 26.5
  TOP w0.135: R63.2 v1(84.3,-31.78) ; v1(75.95,-27.91) 75.63,-28.23 75.15,-28.23 74.68,-27.76 74.68,-26.6 74.36,-26.29 73.97,-26.29 73.66,-26.6 73.66,-28.19 72.95,-28.91 R54.1 69.47,-28.67 69.47,-28.07 69.93,-27.61 70.38,-27.61 70.71,-27.94 U2.16
  BOTTOM w0.135: v1(84.3,-31.78) 84.88,-31.78 85.01,-31.64 85.01,-30.5 84.88,-30.37 78.4,-30.37 v1(75.95,-27.91)
OSPI0_CLK_R: length 6.4
  TOP w0.102: 83.6,-37.97 83.6,-38.16 83.11,-38.64 83.11,-39.04 U18.P20
  TOP w0.135: R63.1 84.3,-34.09 83.6,-34.79 83.6,-37.97
OSPI0_CS0_N: length 32.8
  TOP w0.102: U18.L20 81.61,-39.03 81.61,-38.46
  TOP w0.135: v1(77.39,-26.44) 77.39,-25.51 77.26,-25.37 75.9,-25.37 75.77,-25.51 75.77,-26.64 76.48,-27.36 78.03,-27.36 82.02,-31.34 82.02,-35 81.63,-35.39 81.63,-38.44 81.61,-38.46 ; v1(83.14,-20.33) 83.14,-20.32 U2.7
  BOTTOM w0.135: v1(83.14,-20.33) 82.01,-20.33 R183.1 81.69,-21.92 79.63,-23.98 77.72,-23.98 76.86,-24.84 76.86,-25.91 v1(77.39,-26.44)
OSPI0_D0: length 35.2
  TOP w0.102: U18.L19 82.41,-39.82 v2(82.44,-39.78)
  TOP w0.135: U2.15 70.47,-26.67 R36.1 70.01,-25.87 v1(70.56,-25.32)
  L03_SIG1 w0.121: v2(82.44,-39.78) 83.02,-39.2 83.02,-35.35 82.69,-35.01 82.69,-28.71 80.08,-26.1 78.54,-26.1 78.23,-26.42 78.23,-27.74 77.19,-28.78 74.22,-28.78 73.55,-28.11 73.55,-27.84 73.75,-27.64 73.75,-27.47 73.58,-27.3 73.41,-27.3 73.06,-27.65 72.89,-27.65 72.72,-27.48 72.72,-27.31 73.06,-26.96 73.06,-26.79 72.89,-26.62 72.72,-26.62 72.37,-26.97 72.2,-26.97 72.03,-26.79 72.03,-26.62 72.38,-26.27 72.38,-26.1 72.21,-25.93 72.04,-25.93 71.69,-26.28 71.52,-26.28 v1(70.56,-25.32)
OSPI0_D1: length 35.7
  TOP w0.102: U18.N20 82.89,-38.5 83.33,-38.06 83.33,-37.97
  TOP w0.135: 83.33,-37.97 83.33,-32.03 85.57,-29.79 85.57,-21.88 85.44,-21.75 84.16,-21.75 84.02,-21.61 84.02,-21.32 84.16,-21.18 86.73,-21.18 86.87,-21.05 86.87,-20.75 86.73,-20.62 83.88,-20.62 83.74,-20.48 83.74,-20.16 83.88,-20.03 86.25,-20.03 86.41,-19.87 86.41,-19.53 86.24,-19.37 84.95,-19.37 84.63,-19.05 R10.1 U2.8
OSPI0_D2: length 35.7
  TOP w0.102: U18.L21 81.89,-37.98 81.9,-37.97
  TOP w0.135: U2.9 72.04,-17.58 R5.1 73.29,-17.46 74.61,-18.78 74.61,-20.54 73.79,-21.35 73.79,-21.54 73.98,-21.73 74.17,-21.73 74.99,-20.92 75.18,-20.92 75.37,-21.11 75.37,-21.3 74.55,-22.11 74.55,-22.3 74.74,-22.5 74.93,-22.5 75.75,-21.68 75.94,-21.68 76.13,-21.87 76.13,-22.06 75.31,-22.88 75.31,-23.07 75.5,-23.26 75.69,-23.26 76.51,-22.44 76.77,-22.44 77.98,-23.65 77.98,-26.92 82.38,-31.33 82.38,-35.07 81.9,-35.55 81.9,-37.97
OSPI0_D3: length 35.3
  TOP w0.102: U18.N19 83.33,-39.82 v2(83.37,-39.78)
  TOP w0.135: v1(83.36,-27.94) 83.72,-27.58 83.72,-26.7 83.54,-26.52 R37.1 82.98,-26.52 82.8,-26.7 82.8,-27.81 82.67,-27.94 U2.1
  L03_SIG1 w0.121: v1(83.36,-27.94) 83.05,-27.63 83.05,-26.72 81.93,-25.6 81.2,-25.6 80.72,-26.09 80.72,-26.32 81.15,-26.75 81.42,-26.75 81.82,-26.34 82.02,-26.34 82.31,-26.64 82.31,-26.81 81.85,-27.27 81.85,-27.44 83.21,-28.8 84.18,-28.8 84.3,-28.92 84.3,-29.44 84.18,-29.57 83.82,-29.57 83.62,-29.77 83.62,-30.17 83.74,-30.29 85.27,-30.29 85.39,-30.42 85.39,-30.66 85.27,-30.78 83.74,-30.78 83.62,-30.9 83.62,-31.14 83.74,-31.26 85.05,-31.26 85.17,-31.38 85.17,-32.11 84.94,-32.33 83.06,-32.33 82.94,-32.45 82.94,-32.95 83.06,-33.07 83.67,-33.07 83.79,-33.19 83.79,-33.5 83.29,-34.01 83.29,-39.7 v2(83.37,-39.78)
OSPI0_DQS: length 45.9
  TOP w0.102: v2(83.94,-40.35) 83.45,-40.82 U18.P17
  L03_SIG1 w0.121: v1(95.81,-33.3) 98.56,-33.3 98.73,-33.48 98.73,-34.35 98.56,-34.52 93.94,-34.52 93.82,-34.4 93.82,-33.49 93.7,-33.37 93.46,-33.37 93.34,-33.49 93.34,-34.4 93.22,-34.52 92.98,-34.52 92.85,-34.4 92.85,-33.49 92.73,-33.37 92.49,-33.37 92.37,-33.49 92.37,-34.4 92.25,-34.52 92.01,-34.52 91.89,-34.4 91.89,-33.49 91.77,-33.37 91.53,-33.37 91.41,-33.49 91.41,-34.4 91.29,-34.52 91.04,-34.52 90.92,-34.4 90.92,-33.49 90.8,-33.37 90.56,-33.37 90.44,-33.49 90.44,-34.4 90.32,-34.52 90.08,-34.52 89.96,-34.4 89.96,-33.49 89.84,-33.37 89.22,-33.37 88.29,-32.44 87.77,-32.44 87.53,-32.69 87.53,-35.43 87.38,-35.59 86.64,-35.59 86.44,-35.38 86.44,-32.61 86.18,-32.36 85.65,-32.36 83.88,-34.13 83.88,-38.36 84.3,-38.79 84.3,-39.98 v2(83.94,-40.35)
  BOTTOM w0.135: v1(95.81,-33.3) 95.38,-32.87 95.38,-30.22 95.78,-29.83 R213.1
OSPI0_DQS_R: length 16.7
  TOP w0.135: v1(84.81,-27.33) 84.81,-28.34 83.8,-29.36 R65.1
  L03_SIG1 w0.121: v1(96.55,-28.85) 96.12,-29.28 91.71,-29.28 90.75,-28.32 90.12,-28.32 89.84,-28.6 86.63,-28.6 85.37,-27.33 v1(84.81,-27.33)
  BOTTOM w0.135: R213.2 96.52,-28.85 96.52,-28.85 v1(96.55,-28.85)
OSPI0_LBCLKO: length 9
  TOP w0.102: U18.M21 82.17,-38.59 82.17,-37.97
  TOP w0.135: R65.2 82.65,-30.89 82.65,-35.18 82.17,-35.66 82.17,-35.71 82.17,-35.71 82.17,-37.97
PORZ_OUT: length 224.4
  TOP w0.102: v2(77.86,-39.78) 77.86,-39.77 77.86,-39.78 v2(77.86,-39.78) ; v2(77.86,-39.78) U18.D18
  TOP w0.135: R87.2 72.61,-35.39 72.42,-35.2 TP14.1 72.24,-34.49 v1(72.24,-33.83) ; v1(139.95,-55.35) 139.27,-54.66 133.68,-54.66 130.96,-51.94 130.96,-41.78 135.03,-37.72 138.61,-37.72 139.7,-36.63 v1(139.7,-35.31) 139.32,-34.92 132.49,-34.92 130.73,-33.17 130.73,-30.68 129.36,-29.31 126.64,-29.31 126.54,-29.41 125.53,-29.41 123.65,-27.54 123.65,-21.84 121.11,-19.3 v1(118.24,-19.3) 118.24,-14.91 117,-13.68 85.76,-13.68 82.12,-17.32 80.09,-17.32 78.94,-18.47 v1(78.94,-21.83)
  L03_SIG1 w0.121: v2(77.86,-39.78) 77.45,-39.37 71.2,-39.37 70.11,-38.28 70.11,-34.92 71.2,-33.83 v1(72.24,-33.83) ; v1(39.17,-23.24) 40.26,-22.15 64.05,-22.15 64.53,-21.67 67.47,-21.67 67.86,-22.06 75.46,-22.06 76.05,-22.66 78.11,-22.66 v1(78.94,-21.83)
  BOTTOM w0.135: U28.2 v1(39.17,-23.24) ; U43.2 v1(139.95,-55.35) ; v1(72.24,-33.83) 73.21,-33.83 73.48,-33.55 73.48,-29.79 71.15,-27.46 67.92,-27.46 64.19,-23.72 64.19,-21.59 64.85,-20.93 65.23,-20.93 65.79,-20.37 65.79,-19.51 66.32,-18.97 67.87,-18.97 72.6,-23.71 78.15,-23.71 78.94,-22.91 v1(78.94,-21.83) 78.94,-20.48 78.55,-20.08 R179.1 ; v1(118.24,-19.3) 117.86,-19.68 117.86,-23.04 118.37,-23.56 U32.8 ; U34.2 139.4,-36.05 139.7,-35.75 v1(139.7,-35.31)
PRG1_CPSW_ETH1_CLK_OUT: length 2.7
  TOP w0.135: U19.40 138.68,-49.96 138.98,-50.26 138.98,-50.97 138.79,-51.16 TP33.1
PRG1_CPSW_ETH1_D0M: length 31.5
  TOP w0.102: J19.10 170.26,-43.57 169.81,-43.11 168.43,-43.11 166.53,-45.01 166.53,-46.38 164.92,-48 144.18,-48 144.08,-47.89 U19.2
PRG1_CPSW_ETH1_D0P: length 31.5
  TOP w0.102: U19.1 144.08,-48.39 144.18,-48.29 165.04,-48.29 166.83,-46.51 166.83,-45.14 168.55,-43.41 169.69,-43.41 170.29,-44.01 170.29,-44.4 169.85,-44.84 J19.9
PRG1_CPSW_ETH1_D1M: length 30.2
  TOP w0.102: v1(164.13,-46.19) 163.83,-46.5 144.18,-46.5 144.08,-46.39 U19.5
  BOTTOM w0.102: v1(164.13,-46.19) 163.87,-46.19 163.78,-46.28 163.78,-46.52 163.89,-46.63 ; 170.24,-45.98 170.6,-46.33 171.64,-46.33 J19.8
  BOTTOM w0.135: 170.24,-45.98 167.86,-45.98 167.21,-46.63 164.32,-46.63 164.32,-46.63 163.95,-46.63 163.95,-46.63 163.89,-46.63
PRG1_CPSW_ETH1_D1P: length 30.2
  TOP w0.102: U19.4 144.08,-46.89 144.18,-46.79 163.83,-46.79 v1(164.13,-47.1)
  BOTTOM w0.102: J19.7 169.75,-47.8 170.31,-47.8 ; v1(164.13,-47.1) 164.3,-46.93
  BOTTOM w0.135: 164.3,-46.93 167.37,-46.93 168.02,-46.28 170.12,-46.28 170.56,-46.72 170.56,-47.56 170.31,-47.8
PRG1_CPSW_ETH1_D2M: length 41.5
  TOP w0.102: J19.6 171.41,-49.1 170.82,-49.1 170.64,-48.93 170.64,-48.13 171.27,-47.5 172.78,-47.5 173.26,-47.02 173.26,-42.65 172.14,-41.53 168.06,-41.53 164.59,-45 144.18,-45 144.08,-44.89 U19.8
PRG1_CPSW_ETH1_D2P: length 41.5
  TOP w0.102: U19.7 144.08,-45.39 144.18,-45.29 164.71,-45.29 168.18,-41.83 172.02,-41.83 172.96,-42.77 172.96,-46.89 172.66,-47.2 171.15,-47.2 170.35,-48 170.35,-49.81 170.25,-49.92 J19.5
PRG1_CPSW_ETH1_D3M: length 44.3
  TOP w0.102: U19.11 144.08,-43.39 144.18,-43.5 163.57,-43.5 v1(163.88,-43.19)
  BOTTOM w0.102: v1(163.88,-43.19) 163.65,-43.19 163.53,-43.31 163.53,-43.53 163.64,-43.65 166.85,-43.65 168.36,-42.15 172.73,-42.15 173.71,-43.13 173.71,-49.28 172.95,-50.04 171.36,-50.04 170.76,-50.63 170.76,-51.36 171.02,-51.61 171.44,-51.61 J19.4
PRG1_CPSW_ETH1_D3P: length 44.3
  TOP w0.102: v1(163.88,-44.1) 163.57,-43.79 144.18,-43.79 144.08,-43.89 U19.10
  BOTTOM w0.102: v1(163.88,-44.1) 164.04,-43.95 166.98,-43.95 168.48,-42.44 172.6,-42.44 173.41,-43.25 173.41,-49.16 172.83,-49.74 171.23,-49.74 170.47,-50.51 170.47,-52.79 170.29,-52.96 169.83,-52.96 J19.3
PRG1_CPSW_ETH1_LED1: length 26.2
  BOTTOM w0.135: Q13.5 Q13.6 ; Q13.6 164.24,-41.11 Q13.8 163.59,-41.11 Q13.1 Q13.2 ; Q13.6 172.91,-41.11 175.64,-38.38 181.95,-38.38 182.79,-39.22 J19.12
PRG1_CPSW_ETH1_LED2: length 34.9
  L03_SIG1 w0.121: J19.13 176.28,-60.48 170.94,-60.48 169.6,-59.13 169.6,-57.73 165.23,-53.37 165.23,-51.08 v1(161.47,-47.32)
  BOTTOM w0.135: R252.1 157.92,-47.71 158.3,-47.34 Q14.1 ; Q14.6 160.1,-47.34 Q14.8 159.45,-47.34 Q14.1 ; Q14.6 Q14.5 ; Q14.6 160.76,-47.32 v1(161.47,-47.32) ; Q14.1 Q14.2
PRG1_CPSW_ETH1_LED3: length 41.2
  L03_SIG1 w0.121: v1(161.47,-44.42) 160.91,-44.98 160.91,-47.98 161.8,-48.87 162.61,-48.87 164.9,-51.16 164.9,-53.54 169.11,-57.76 169.11,-59.03 170.89,-60.81 177.98,-60.81 J19.14
  BOTTOM w0.135: Q15.6 160.1,-44.44 Q15.8 159.45,-44.44 Q15.1 ; Q15.6 160.76,-44.42 v1(161.47,-44.42) ; Q15.6 Q15.5 ; Q15.2 Q15.1 ; Q15.1 157,-44.44 R257.1
PRG1_CPSW_ETH1_LED_1000/RX_ER: length 97.7
  TOP w0.102: U18.U14 84.62,-42.58 84.62,-42.58 v2(84.38,-42.82)
  TOP w0.135: v1(145.56,-51.28) 145.32,-51.51 145,-51.51 R138.1 144.76,-50.73 144.61,-50.57 142.42,-50.57 141.68,-49.83 U19.46
  L03_SIG1 w0.121: v2(84.38,-42.82) 84.49,-42.71 86.62,-42.71 87.35,-41.99 97.94,-41.99 99.77,-43.81 105.56,-43.81 105.97,-43.41 105.97,-42.37 108.76,-39.58 117.06,-39.58 v1(117.47,-39.16) ; v1(145.56,-51.28) 144.96,-50.67 143.13,-50.67 142.55,-50.09 142.55,-42.98 140.34,-40.77 v1(129.41,-40.77)
  BOTTOM w0.135: R138.1 v1(145.56,-51.28) 146.29,-50.55 147.07,-50.55 152.27,-45.34 158.52,-45.34 158.8,-45.61 Q14.3 ; v1(117.47,-39.16) 119.39,-41.08 129.1,-41.08 v1(129.41,-40.77)
PRG1_CPSW_ETH1_LED_ACT: length 84.9
  TOP w0.135: U19.45 141.18,-49.82 142.21,-50.84 142.81,-50.84 143.25,-51.28 R137.1 143.5,-51.49 143.81,-51.49 v1(144.02,-51.28) ; v1(104.01,-42.24) 104.01,-41.66 105.16,-40.51 105.79,-40.51 109.43,-36.88 113.71,-36.88 116.71,-39.88 v1(123.06,-39.88)
  L03_SIG1 w0.121: v1(123.06,-39.88) 123.95,-40.77 128.52,-40.77 128.95,-41.19 137.33,-41.19 138.18,-42.04 141.1,-42.04 142.29,-43.23 142.29,-50.22 143.36,-51.28 v1(144.02,-51.28)
  BOTTOM w0.135: Q13.3 162.37,-39.81 162.05,-40.13 162.05,-44.58 161.54,-45.08 158.65,-45.08 158.63,-45.07 152.03,-45.07 146.94,-50.16 144.69,-50.16 144.02,-50.83 v1(144.02,-51.28) 144.01,-51.28 R137.1 ; R594.2 v1(104.01,-42.24)
PRG1_CPSW_ETH1_LED_LINK: length 82.9
  TOP w0.102: 87.74,-42.98 87.13,-42.98 87.01,-43.09 86.67,-43.09 U18.Y13
  TOP w0.135: v1(147.39,-51.28) 147.18,-51.49 146.8,-51.49 R139.1 146.59,-50.73 146.15,-50.29 142.64,-50.29 142.18,-49.83 U19.47 ; 87.74,-42.98 95.2,-42.98 97.28,-40.89 99.44,-40.89 99.74,-40.59 101.24,-40.59 101.93,-41.27 102.64,-41.27 103,-40.92 103,-40 103.96,-39.04 105.87,-39.04 108.08,-36.83 108.68,-36.83 108.9,-36.61 114.08,-36.61 115.95,-38.48 123.06,-38.48 v1(124.46,-39.88)
  L03_SIG1 w0.121: v1(147.39,-51.28) 146.41,-50.29 143.22,-50.29 142.94,-50.01 142.94,-43.02 142.8,-42.87 139.81,-39.88 v1(124.46,-39.88)
  BOTTOM w0.135: R139.1 v1(147.39,-51.28)
PRG1_CPSW_ETH1_RBIAS: length 1.3
  TOP w0.254: U19.12 R102.1
PRG1_CPSW_ETH2_CLK_OUT: length 2.6
  TOP w0.135: TP11.1 138.68,-32.53 U7.40
PRG1_CPSW_ETH2_D0M: length 34.2
  TOP w0.102: J18.10 170.26,-21.72 169.81,-21.26 168.46,-21.26 167.19,-22.53 167.19,-26.63 164.87,-28.95 144.18,-28.95 144.08,-28.84 U7.2
PRG1_CPSW_ETH2_D0P: length 34.2
  TOP w0.102: J18.9 169.83,-22.99 170.26,-22.56 170.26,-22.14 169.69,-21.56 168.58,-21.56 167.49,-22.66 167.49,-26.75 164.99,-29.24 144.18,-29.24 144.08,-29.34 U7.1
PRG1_CPSW_ETH2_D1M: length 31.3
  TOP w0.102: v1(163.88,-27.14) 163.57,-27.45 144.18,-27.45 144.08,-27.34 U7.5
  BOTTOM w0.102: J18.8 171.64,-24.49 170.66,-24.49 170.3,-24.13 168.18,-24.13 164.73,-27.58 163.63,-27.58 163.5,-27.46 163.5,-27.29 163.65,-27.14 v1(163.88,-27.14)
PRG1_CPSW_ETH2_D1P: length 31.3
  TOP w0.102: v1(163.88,-28.05) 163.57,-27.74 144.18,-27.74 144.08,-27.84 U7.4
  BOTTOM w0.102: J18.7 169.73,-25.93 170.34,-25.93 170.52,-25.76 170.52,-24.76 170.18,-24.43 168.31,-24.43 164.85,-27.88 164.05,-27.88 v1(163.88,-28.05)
PRG1_CPSW_ETH2_D2M: length 44.5
  TOP w0.102: U7.8 144.08,-25.84 144.18,-25.95 164,-25.95 165.67,-24.27 165.67,-21.47 167.45,-19.68 172.14,-19.68 173.52,-21.05 173.52,-24.91 172.78,-25.65 171.27,-25.65 170.64,-26.28 170.64,-27.08 170.77,-27.2 171.46,-27.2 J18.6
PRG1_CPSW_ETH2_D2P: length 44.5
  TOP w0.102: J18.5 170.18,-28.07 170.35,-27.9 170.35,-26.15 171.15,-25.35 172.66,-25.35 173.22,-24.79 173.22,-21.17 172.02,-19.98 167.58,-19.98 165.96,-21.59 165.96,-24.4 164.12,-26.24 144.18,-26.24 144.08,-26.34 U7.7
PRG1_CPSW_ETH2_D3M: length 45.5
  TOP w0.135: v1(163.88,-24.14) 163.56,-24.45 144.23,-24.45 144.12,-24.34 U7.11
  BOTTOM w0.102: J18.4 171.46,-29.74 171,-29.74 170.76,-29.51 170.76,-28.78 171.36,-28.19 172.95,-28.19 173.71,-27.43 173.71,-21.29 172.67,-20.24 169.07,-20.24 164.74,-24.57 163.6,-24.57 163.5,-24.47 163.5,-24.24 163.6,-24.14 v1(163.88,-24.14)
PRG1_CPSW_ETH2_D3P: length 45.5
  TOP w0.135: U7.10 144.12,-24.84 144.23,-24.73 163.56,-24.73 v1(163.88,-25.05)
  BOTTOM w0.102: v1(163.88,-25.05) 164.06,-24.87 164.87,-24.87 169.2,-20.54 172.55,-20.54 173.41,-21.41 173.41,-27.31 172.83,-27.89 171.23,-27.89 170.47,-28.66 170.47,-30.94 170.29,-31.11 169.83,-31.11 J18.3
PRG1_CPSW_ETH2_LED1: length 24.4
  BOTTOM w0.135: J18.12 182.79,-19 181.44,-17.65 170.03,-17.65 166.85,-20.83 Q10.5 Q10.6 164.79,-21.48 Q10.8 164.14,-21.48 Q10.1 Q10.2
PRG1_CPSW_ETH2_LED2: length 23.1
  L03_SIG1 w0.121: v1(165.68,-37.24) 166.7,-38.25 176.66,-38.25 J18.13
  BOTTOM w0.135: R220.1 161.93,-37.88 161.94,-37.89 Q11.1 ; Q11.2 Q11.1 ; Q11.1 163.59,-37.89 Q11.8 164.24,-37.89 Q11.6 Q11.5 v1(165.68,-37.24)
PRG1_CPSW_ETH2_LED3: length 29.1
  L03_SIG1 w0.121: J18.14 178.34,-38.61 166.37,-38.61 165.23,-37.46 165.23,-36.58 165.68,-36.12 v1(165.68,-34.34)
  BOTTOM w0.135: R223.1 162.93,-34.98 Q12.1 ; Q12.1 163.59,-34.99 Q12.8 164.24,-34.99 Q12.6 Q12.5 v1(165.68,-34.34) ; Q12.1 Q12.2
PRG1_CPSW_ETH2_LED_1000/RX_ER: length 105.5
  TOP w0.102: U18.AA11 87.12,-44.04 87.57,-44.04 87.58,-44.05
  TOP w0.135: 87.58,-44.05 88.57,-44.05 89.16,-44.64 96.97,-44.64 98.73,-42.88 v1(98.73,-42.11) ; v1(143.99,-32.23) 143.77,-32.44 143.5,-32.44 R75.1 143.29,-31.78 143.08,-31.57 142.42,-31.57 141.68,-30.84 U7.46
  L03_SIG1 w0.121: v1(109.6,-35.56) 110.47,-35.56 113.14,-32.89 114.35,-32.89 114.7,-32.54 114.7,-31.93 119.56,-27.07 119.56,-25.53 121.49,-23.59 127.68,-23.59 128.44,-22.84 133.98,-22.84 134.32,-22.5 135.8,-22.5 136.6,-23.3 140.14,-23.3 142.75,-25.91 142.75,-30.99 v1(143.99,-32.23)
  BOTTOM w0.135: Q11.3 162.94,-36.06 162.56,-35.69 160.92,-35.69 160.66,-35.43 160.66,-31.5 160.02,-30.86 149.89,-30.86 149.12,-31.62 148.72,-31.62 148.7,-31.64 144.57,-31.64 v1(143.99,-32.23) R75.1 ; v1(98.73,-42.11) 98.73,-40.51 102.79,-36.45 108.71,-36.45 v1(109.6,-35.56)
PRG1_CPSW_ETH2_LED_ACT: length 92.1
  TOP w0.135: v1(99.06,-37.08) 99.07,-37.07 R596.2 ; U7.45 141.18,-30.92 141.79,-31.53 R74.1 142,-32.44 142.32,-32.44 v1(142.52,-32.23)
  L03_SIG1 w0.121: v1(99.06,-37.08) 100.33,-37.08 101.13,-36.28 111.31,-36.28 114.95,-32.64 114.95,-32.04 119.99,-27 119.99,-25.46 121.6,-23.85 127.78,-23.85 128.54,-23.09 134.09,-23.09 134.43,-22.75 135.69,-22.75 136.49,-23.55 140.03,-23.55 142.11,-25.63 142.11,-31.83 v1(142.52,-32.23)
  BOTTOM w0.135: Q10.3 162.2,-20.18 161.54,-20.84 161.54,-25.65 157.86,-29.34 150.62,-29.34 148.59,-31.37 142.93,-31.37 142.52,-31.78 v1(142.52,-32.23) 142.51,-32.23 R227.2
PRG1_CPSW_ETH2_LED_LINK: length 79.4
  TOP w0.102: v2(85.93,-44.27) 85.89,-44.24 U18.W11
  TOP w0.135: U7.47 142.18,-30.88 142.57,-31.27 144.61,-31.27 145.01,-31.68 R76.1 145.22,-32.44 145.59,-32.44 v1(145.8,-32.23) 146.53,-32.23 146.81,-32.51 146.81,-34.29 146.18,-34.92 140.97,-34.92 140.59,-34.54 132.62,-34.54 132.28,-34.2 v1(132.28,-33.76)
  L03_SIG1 w0.121: v2(85.93,-44.27) 87.38,-44.27 87.75,-44.65 96.11,-44.65 97.28,-45.82 102.97,-45.82 103.6,-46.45 104.37,-46.45 106.76,-44.07 106.76,-43.26 109.93,-40.09 118.34,-40.09 119.76,-38.67 119.76,-36.32 121.03,-35.05 123.82,-35.05 125.12,-33.76 v1(132.28,-33.76)
  BOTTOM w0.135: R225.2 145.79,-32.23 v1(145.8,-32.23)
PRG1_CPSW_ETH2_RBIAS: length 1.3
  TOP w0.254: U7.12 R22.1
PRG1_CPSW_RGMII1_CLK: length 32.7
  TOP w0.135: R25.2 130.3,-24.31 v1(131.75,-25.76) ; v1(138.96,-41.3) 139.18,-41.52 U19.20
  BOTTOM w0.135: v1(131.75,-25.76) 132.33,-25.76 133.25,-24.84 134.39,-24.84 138.81,-29.26 140.34,-29.26 141.22,-30.15 141.22,-31.98 139.77,-33.43 139.77,-34.5 138.98,-35.3 138.92,-35.3 138.91,-35.31 137.97,-35.31 136.96,-36.32 136.96,-40.64 137.62,-41.3 v1(138.96,-41.3)
PRG1_CPSW_RGMII1_CLK_R: length 2.7
  TOP w0.135: R25.1 126.24,-24.31 125.96,-24.59 125.96,-24.92 125.69,-25.19 U6.8
PRG1_CPSW_RGMII1_GPIO_1: length 26
  TOP w0.135: v1(137.39,-40.34) 137.59,-40.13 137.97,-40.13 R95.2 U19.22
  BOTTOM w0.135: v1(137.39,-40.34) 137.4,-40.34 R95.2 139.02,-40.34 139.7,-41.02 141.86,-41.02 142.24,-40.64 145.92,-40.64 147.45,-42.16 158.37,-42.16 158.8,-42.59 Q15.3
PRG1_CPSW_RGMII1_RD0: length 33.9
  TOP w0.135: v1(133.99,-47.83) 133.78,-48.03 133.78,-48.36 R123.1 134.51,-48.55 134.67,-48.39 134.67,-47.73 135.5,-46.89 U19.33
  L03_SIG1 w0.121: v1(133.99,-47.83) 132.7,-49.12 128.82,-49.12 128.7,-49.24 128.7,-49.59 128.58,-49.71 128.34,-49.71 128.22,-49.59 128.22,-49.24 128.1,-49.12 127.86,-49.12 127.74,-49.24 127.74,-49.59 127.61,-49.71 127.37,-49.71 127.25,-49.59 127.25,-49.24 127.13,-49.12 126.89,-49.12 126.77,-49.24 126.77,-49.59 126.65,-49.71 126.41,-49.71 126.29,-49.59 126.29,-49.24 126.17,-49.12 114.65,-49.12 112.37,-46.84 v1(111.87,-46.84)
  BOTTOM w0.135: v1(111.87,-46.84) 111.37,-46.34 U40.11 ; v1(133.99,-47.83) 133.99,-48.6 R254.2
PRG1_CPSW_RGMII1_RD1: length 33.8
  TOP w0.135: U19.34 135.56,-47.39 134.95,-48.01 134.95,-49.56 134.52,-49.99 R129.2 133.76,-49.77 133.76,-49.53 133.99,-49.3 v1(133.99,-49.29)
  L03_SIG1 w0.121: v1(133.99,-49.29) 132.86,-50.41 122.04,-50.41 121.92,-50.29 121.92,-50.01 121.8,-49.89 121.55,-49.89 121.43,-50.01 121.43,-50.29 121.31,-50.41 121.07,-50.41 120.95,-50.29 120.95,-50.01 120.83,-49.89 120.59,-49.89 120.47,-50.01 120.47,-50.29 120.35,-50.41 115.41,-50.41 112.34,-47.35 111.19,-47.35 v1(110.68,-46.84)
  BOTTOM w0.135: U40.12 v1(110.68,-46.84) ; R129.2 133.99,-49.97 v1(133.99,-49.29)
PRG1_CPSW_RGMII1_RD2: length 31.4
  TOP w0.135: R132.1 133.24,-51.28 ; 133.24,-51.28 133.23,-51.28 v1(132.5,-51.28) ; 133.24,-51.28 133.82,-50.7 134.29,-50.7 135.25,-49.73 135.25,-48.13 135.49,-47.89 U19.35
  L03_SIG1 w0.121: v1(111.87,-47.84) 112.38,-47.84 115.3,-50.76 131.98,-50.76 v1(132.5,-51.28)
  BOTTOM w0.135: v1(111.87,-47.84) 111.37,-47.34 U40.13 ; v1(132.5,-51.28) 132.51,-51.28 R132.1
PRG1_CPSW_RGMII1_RD3: length 35
  TOP w0.135: U19.36 135.74,-48.39 135.53,-48.6 135.53,-49.92 134.73,-50.73 R133.1 134.94,-51.49 135.28,-51.49 135.59,-51.18 v1(135.59,-50.62)
  L03_SIG1 w0.121: v1(135.59,-50.62) 133.76,-50.62 132.68,-51.71 132.33,-51.71 131.7,-51.08 115.09,-51.08 112.34,-48.34 111.18,-48.34 v1(110.68,-47.84)
  BOTTOM w0.135: v1(135.59,-50.62) 134.83,-50.62 134.73,-50.73 R133.1 ; U40.14 v1(110.68,-47.84)
PRG1_CPSW_RGMII1_RSTN: length 5.9
  TOP w0.135: U19.43 140.18,-50.14 v1(140.61,-50.57)
  BOTTOM w0.135: v1(140.61,-50.57) 140.61,-51.82 139.85,-52.58 139.19,-52.58 139,-52.77 U43.4
PRG1_CPSW_RGMII1_RX_CTL: length 34
  TOP w0.135: U19.38 137.68,-49.83 137.58,-49.94 136.6,-49.94 136.22,-50.31 R134.2 136.92,-51.28 v1(136.93,-51.28)
  L03_SIG1 w0.121: v1(136.93,-51.28) 136.6,-51.61 133.53,-51.61 132.87,-52.27 131.88,-52.27 131.62,-52.02 118.52,-52.02 117.88,-51.38 114.93,-51.38 112.39,-48.84 v1(111.87,-48.84)
  BOTTOM w0.135: v1(136.93,-51.28) 136.92,-51.28 R134.2 ; U40.15 111.37,-48.34 v1(111.87,-48.84)
PRG1_CPSW_RGMII1_RXC: length 30.4
  TOP w0.135: v1(132.28,-47.12) 132.95,-47.12 R115.1
  L03_SIG1 w0.121: v1(110.68,-48.84) 110.68,-49.48 110.35,-49.81 109.86,-49.81 109.5,-49.45 109.5,-46.71 109.88,-46.33 113.61,-46.33 115.13,-47.85 131.55,-47.85 v1(132.28,-47.12)
  BOTTOM w0.135: U40.16 v1(110.68,-48.84)
PRG1_CPSW_RGMII1_RXC_R: length 2.8
  TOP w0.135: R115.2 134.5,-47.1 135.21,-46.39 U19.32
